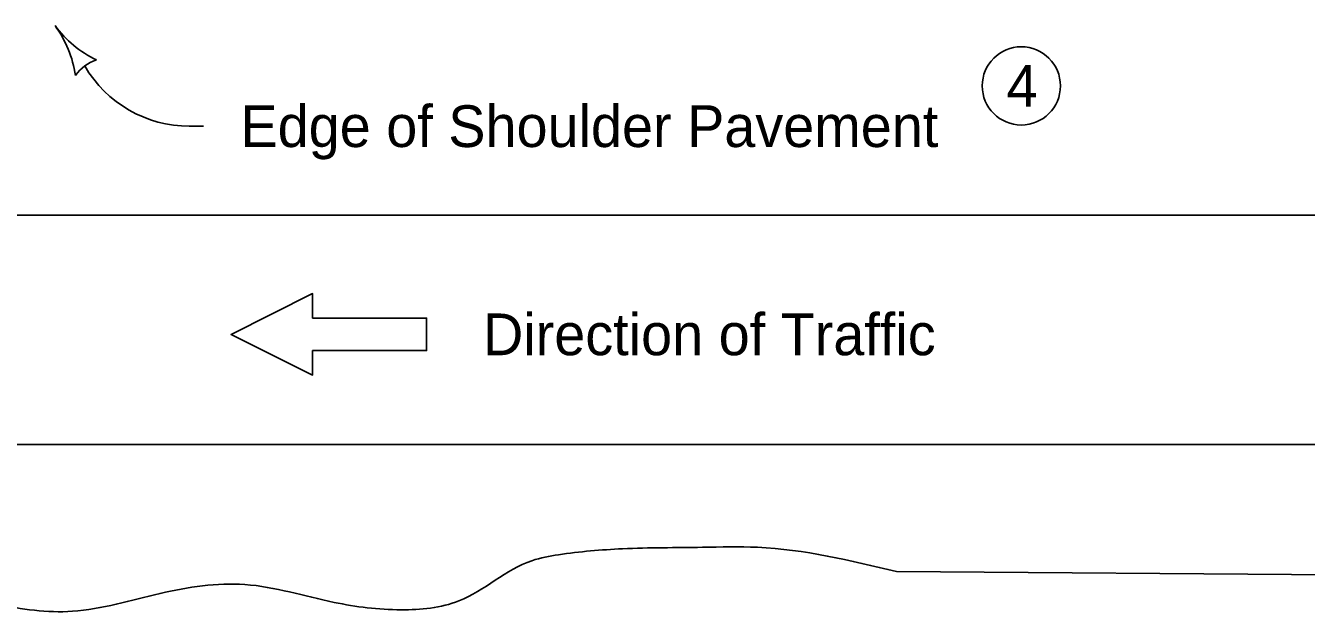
# Model space of a CAD drawing. Extents: x 6410 to 81668, y 3928 to 11667.
# Drawn here: x 11038.4 to 11529.5, y 9461 to 9688.2 of the extents above; entities that cross this region are included whole.
import ezdxf

# ---------------------------------------------------------------- set-up
doc = ezdxf.new("R2010")
doc.units = 0
for name, color, linetype in [('dsnCellElements', 7, 'Continuous'), ('dsnStdBlockModified', 7, 'Continuous'), ('dsnStdLineWork', 7, 'Continuous'), ('Level 11', 7, 'Continuous'), ('Level 12', 7, 'Continuous'), ('Level 7', 7, 'Continuous')]:
    doc.layers.add(name, color=color, linetype=linetype)

msp = doc.modelspace()

# ---------------------------------------------------------------- linework, layer by layer
at = {"layer": 'dsnCellElements'}
msp.add_line((11101.1, 9649.65), (11106.55, 9649.65), dxfattribs=at)
for centre, radius, start, end in [((11083.84, 9713.4), 42.5, 216.3726, 244.445), ((11015.4, 9662.99), 42.5, 8.3001, 36.3726), ((11070.75, 9659.5), 16.42, 108.6392, 144.1059), ((11101.16, 9696.11), 46.46, 210.2274, 270)]:
    msp.add_arc(centre, radius, start, end, dxfattribs=at)
at = {"layer": 'dsnStdBlockModified'}
for p, q in [((10369.86, 9615.54), (11983.65, 9615.54)), ((11372.34, 9478.91), (11701.54, 9476.45))]:
    msp.add_line(p, q, dxfattribs=at)
msp.add_spline([(10373.93, 9471.82), (10383.36, 9474.4), (10413.58, 9473.83), (10441.52, 9465.84), (10468.89, 9464.7), (10487.14, 9470.4), (10513.94, 9469.83), (10538.46, 9465.27), (10562.41, 9468.69), (10579.52, 9473.83), (10619.43, 9466.41), (10646.23, 9462.42), (10670.75, 9471.54), (10693.56, 9473.26), (10732.34, 9467.55), (10731.77, 9467.55), (10752.92, 9465.95), (10789.99, 9468.8), (10815.08, 9471.65), (10833.9, 9475.08), (10857.85, 9474.5), (10879.51, 9471.08), (10905.17, 9466.52), (10938.82, 9467.66), (10970.18, 9473.93), (10995.27, 9473.93), (11027.2, 9466.52), (11056.29, 9463.67), (11089.93, 9470.51), (11122.43, 9473.93), (11156.65, 9467.09), (11182.31, 9464.24), (11204.54, 9467.66), (11232.49, 9483.06), (11242.75, 9485.34), (11267.27, 9487.63), (11297.93, 9488.2), (11319.03, 9488.2), (11372.34, 9478.91)], degree=3, dxfattribs=at)
at = {"layer": 'dsnStdLineWork'}
msp.add_lwpolyline([(11148.4, 9576.09), (11148.4, 9585.47), (11117.15, 9569.84), (11148.4, 9554.22), (11148.4, 9563.59), (11192.15, 9563.59), (11192.15, 9576.09), (11148.4, 9576.09)], dxfattribs=at)
at = {"layer": 'Level 11'}
msp.add_line((10353.26, 9527.62), (11995.29, 9527.62), dxfattribs=at)
at = {"layer": 'Level 12'}
msp.add_lwpolyline([(11192.15, 9576.09), (11192.15, 9563.59), (11148.4, 9563.59), (11148.4, 9554.22), (11117.15, 9569.84), (11148.4, 9585.47), (11148.4, 9576.09)], close=True, dxfattribs=at)
at = {"layer": 'Level 7'}
msp.add_circle((11420.2, 9665.08), 15, dxfattribs=at)

# ---------------------------------------------------------------- texts
at = {"layer": 'dsnCellElements'}
for s, p in [('Edge of Shoulder Pavement', (11120.74, 9641.65)), ('Direction of Traffic', (11213.76, 9561.84))]:
    msp.add_text(s, height=16, dxfattribs=at).set_placement(p)
at = {"layer": 'Level 7'}
msp.add_text('4', height=16, dxfattribs=at).set_placement((11414.53, 9657.08))

doc.saveas('drawing.dxf')
